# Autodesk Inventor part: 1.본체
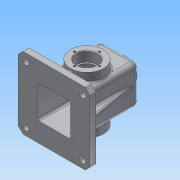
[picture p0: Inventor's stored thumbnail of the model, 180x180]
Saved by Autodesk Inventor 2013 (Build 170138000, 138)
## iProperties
Created: 2018-10
Part Number: 1.본체
Material: 알루미늄 6061
Document SubType Name: Modeling
Designer: Administrator
Density: 2.71 g/cm^3
Mass: 789.687 g
Surface Area: 898.798 cm^2
Volume: 291.397 cm^3
Author: Administrator
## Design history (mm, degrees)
sketch "스케치1"
  geometry: C1 r 27.5 at (0, 0); 1 further point
  constraints: 1 centre point, 1 coincident
  dimensions: "d0" = 55 diameter of C1
extrude "돌출1" new body sketch "스케치1" stored distance "d2" = 95; taper "d3" = 0 deg
node "작업 평면1"
sketch "스케치3"
  geometry: L1 (60, -60)-(-60, -60); L2 (-60, -60)-(-60, 60); L3 (-60, 60)-(60, 60); L4 (60, 60)-(60, -60); L5 (60, -60)-(-60, 60); L6 (-60, -60)-(60, 60); 1 further point
  constraints: 12 end point, 2 midpoint, 2 parallel, 1 horizontal, 1 perpendicular
  dimensions: "d5" = 120 distance of L1.start L1.end; "d7" = 120 distance of L1.end L2.end
extrude "돌출2" join sketch "스케치3" distance "d8" = 10; taper "d9" = 0 deg
sketch "스케치4"
  geometry: L1 (-32.5, 32.5)-(32.5, 32.5); L2 (32.5, 32.5)-(32.5, -32.5); L3 (32.5, -32.5)-(-32.5, -32.5); L4 (-32.5, -32.5)-(-32.5, 32.5); L5 (-32.5, 32.5)-(32.5, -32.5); L6 (32.5, 32.5)-(-32.5, -32.5); 1 further point
  constraints: 12 end point, 2 midpoint, 2 parallel, 1 horizontal, 1 perpendicular
  dimensions: "d10" = 65 distance of L1.start L1.end; "d12" = 65 distance of L1.end L2.end
extrude "돌출3" join sketch "스케치4" distance "d13" = 100; taper "d14" = 0 deg
chamfer "모따기1" distance "d15" = 8; stored, may be unused: second distance "d16" = 2, angle "d17" = 45 deg
sketch "스케치5"
  geometry: 3 further points
  dimensions: "d18" = 95 distance of point (47.5, 47.5) point (-47.5, 47.5); "d20" = 47.5 horizontal distance of point (-47.5, 47.5) point (0, 0); "d21" = 47.5 horizontal distance of point (0, 0) point (-47.5, 47.5); "d22" = 47.5 horizontal distance of point (0, 0) point (47.5, 47.5)
hole "구멍1" sketch "스케치5" at (-47.5, 47.5), (47.5, 47.5) diameter "d23" = 10; stored, may be unused: countersink angle "d27" = 90 deg, drill point angle "d29" = 118 deg; dims "d24" = 6, "d25" = 4, "d26" = 2, "d28" = 8
sketch "스케치6"
  geometry: L1 (-27.5, 27.5)-(27.5, 27.5); L2 (27.5, 27.5)-(27.5, -27.5); L3 (27.5, -27.5)-(-27.5, -27.5); L4 (-27.5, -27.5)-(-27.5, 27.5); L5 (-27.5, 27.5)-(27.5, -27.5); L6 (27.5, 27.5)-(-27.5, -27.5); 1 further point
  constraints: 12 end point, 2 midpoint, 2 parallel, 1 horizontal, 1 perpendicular
  dimensions: "d30" = 55 distance of L2.end L3.end; "d31" = 55 distance of L1.end L2.end
extrude "돌출4" cut sketch "스케치6" distance "d32" = 105; taper "d33" = 0 deg
sketch "스케치7"
  geometry: L1 (0, 0)-(21, 0); C1 r 27.5 at (0, 0) reference; 1 further point
  constraints: 2 end point, 1 coincident, 1 horizontal
  dimensions: "d34" = 21 distance of L1.start L1.end
hole "구멍2" sketch "스케치7" at (21, 0) diameter "d35" = 3.242; stored, may be unused: countersink angle "d39" = 90 deg, drill point angle "d41" = 118 deg; dims "d36" = 8, "d37" = 4, "d38" = 2, "d40" = 10
sketch "스케치9"
  geometry: C1 r 27.5 at (0, 0) reference
hole "구멍3" sketch "스케치9" at (0, 0) diameter "d45" = 30; stored, may be unused: countersink angle "d49" = 90 deg, drill point angle "d51" = 118 deg; dims "d46" = 8, "d47" = 35, "d48" = 17, "d50" = 10
sketch "스케치10"
  geometry: C1 r 15 at (0, 0) reference
hole "구멍4" sketch "스케치10" at (0, 0) diameter "d52" = 30; stored, may be unused: countersink angle "d56" = 90 deg, drill point angle "d58" = 118 deg; dims "d53" = 8, "d54" = 35, "d55" = 17, "d57" = 10
fillet "모깎기1" dims "d59" = 3
fillet "모깎기2" dims "d60" = 3
node "작업 평면2"
sketch "스케치11"
  geometry: C1 r 20 at (0, 0); 1 further point
  constraints: 1 centre point, 1 coincident
  dimensions: "d62" = 40 diameter of C1
extrude "돌출5" join sketch "스케치11" stored distance "d64" = 105; taper "d65" = 0 deg
feature "면 기울기1" dims angle "d66" = 7 deg
sketch "스케치13"
  geometry: L1 (32.5, 55)-(32.5, -45) reference; L2 (32.5, -45)-(60, -45) reference; L3 (60, -45)-(60, -55) reference; L4 (60, -55)-(27.5, -55) reference; L5 (27.5, -55)-(27.5, 47) reference; L6 (24.5, 50)-(-24.5, 50) reference; L7 (-18.772, 65)-(18.772, 65) reference; L8 (18.772, 65)-(20, 55) reference; L9 (20, 55)-(32.5, 55) reference; L10 (-32.5, -45)-(-32.5, 55) reference; L11 (-32.5, 55)-(-20, 55) reference; L12 (-20, 55)-(-18.772, 65) reference; L13 (-27.5, 47)-(-27.5, -55) reference; L14 (-27.5, -55)-(-60, -55) reference; L15 (-60, -55)-(-60, -45) reference; L16 (-60, -45)-(-32.5, -45) reference; L17 (-48, -45)-(-32.5, 42.905); A1 r 3 centre (24.5, 47) between (27.5, 47) and (24.5, 50) reference; A2 r 3 centre (-24.5, 47) between (-24.5, 50) and (-27.5, 47) reference; 1 further point
  constraints: 2 end point, 2 point on line
  dimensions: "d75" = 12 distance from line of L15 L17.start; "d76" = 100 deg angle of L16 L17
feature "리브1" sketch "스케치13" dims "d77" = 2, "d78" = 10, "d79" = 0, "d80" = 0, "d81" = 1, "d82" = 1
sketch "스케치14"
  geometry: L1 (-21, -36.526)-(-22.621, -37.5) reference; L2 (-22.621, -37.5)-(-22.621, -47.5) reference; L3 (-22.621, -47.5)-(-27.5, -47.5) reference; L4 (-27.5, -47.5)-(-27.5, -32.5) reference; L5 (-27.5, -32.5)-(-45, -32.5) reference; L6 (-45, -32.5)-(-45, -60) reference; L7 (-45, -60)-(-55, -60) reference; L8 (-55, -60)-(-55, -27.5) reference; L9 (-55, -27.5)-(-15, -27.5) reference; L10 (-15, -27.5)-(-15, -30.5) reference; L11 (-15, -30.5)-(-17.5, -30.5) reference; L12 (-17.5, -30.5)-(-17.5, -47.5) reference; L13 (-17.5, -47.5)-(-19.379, -47.5) reference; L14 (-19.379, -47.5)-(-19.379, -37.5) reference; L15 (-19.379, -37.5)-(-21, -36.526) reference; L16 (-22.621, 37.5)-(-21, 36.526) reference; L17 (-21, 36.526)-(-19.379, 37.5) reference; L18 (-19.379, 37.5)-(-19.379, 47.5) reference; L19 (-19.379, 47.5)-(-17.5, 47.5) reference; L20 (-17.5, 47.5)-(-17.5, 30.5) reference; L21 (-17.5, 30.5)-(-15, 30.5) reference; L22 (-15, 30.5)-(-15, 27.5) reference; L23 (-15, 27.5)-(-55, 27.5) reference; L24 (-55, 27.5)-(-55, 60) reference; L25 (-55, 60)-(-45, 60) reference; L26 (-45, 60)-(-45, 32.5) reference; L27 (-45, 32.5)-(-27.5, 32.5) reference; L28 (-27.5, 32.5)-(-27.5, 47.5) reference; L29 (-27.5, 47.5)-(-22.621, 47.5) reference; L30 (-22.621, 47.5)-(-22.621, 37.5) reference; L31 (27.5, 32.5)-(55, 32.5) reference; L32 (55, 32.5)-(55, 20) reference; L33 (55, 20)-(65, 18.772) reference; L34 (65, 18.772)-(65, -18.772) reference; L35 (50, -24.5)-(50, 24.5) reference; L36 (47, 27.5)-(15, 27.5) reference; L37 (15, 27.5)-(15, 30.5) reference; L38 (15, 30.5)-(17.5, 30.5) reference; L39 (17.5, 30.5)-(17.5, 47.5) reference; L40 (17.5, 47.5)-(19.379, 47.5) reference; L41 (19.379, 47.5)-(19.379, 37.5) reference; L42 (19.379, 37.5)-(21, 36.526) reference; L43 (21, 36.526)-(22.621, 37.5) reference; L44 (22.621, 37.5)-(22.621, 47.5) reference; L45 (22.621, 47.5)-(27.5, 47.5) reference; L46 (27.5, 47.5)-(27.5, 32.5) reference; L47 (55, -32.5)-(27.5, -32.5) reference; L48 (27.5, -32.5)-(27.5, -47.5) reference; L49 (27.5, -47.5)-(22.621, -47.5) reference; L50 (22.621, -47.5)-(22.621, -37.5) reference; L51 (22.621, -37.5)-(21, -36.526) reference; L52 (21, -36.526)-(19.379, -37.5) reference; L53 (19.379, -37.5)-(19.379, -47.5) reference; L54 (19.379, -47.5)-(17.5, -47.5) reference; L55 (17.5, -47.5)-(17.5, -30.5) reference; L56 (17.5, -30.5)-(15, -30.5) reference; L57 (15, -30.5)-(15, -27.5) reference; L58 (15, -27.5)-(47, -27.5) reference; L59 (65, -18.772)-(55, -20) reference; L60 (55, -20)-(55, -32.5) reference; L61 (-45, 42.5)-(-30.759, 42.5); A1 r 3 centre (47, 24.5) between (50, 24.5) and (47, 27.5) reference; A2 r 3 centre (47, -24.5) between (47, -27.5) and (50, -24.5) reference; 1 further point
  constraints: 2 end point, 1 perpendicular, 1 point on line
  dimensions: "d83" = 15 distance between parallel lines of L23 L61
feature "리브2" sketch "스케치14" dims "d84" = 2, "d85" = 6, "d86" = 0, "d87" = 0, "d88" = 1, "d89" = 1
fillet "모깎기3" dims "d90" = 3
fillet "모깎기4" dims "d91" = 0.3
fillet "모깎기5" dims "d92" = 8
fillet "모깎기6" dims "d93" = 8
fillet "모깎기7" dims "d94" = 3
fillet "모깎기8" dims "d95" = 3
fillet "모깎기9" dims "d96" = 3
fillet "모깎기10" dims "d97" = 1
chamfer "모따기2" distance "d98" = 1; stored, may be unused: second distance "d99" = 2, angle "d100" = 45 deg
sketch "스케치15"
  geometry: L1 (-8, 0)-(-8, -91) reference; L2 (5.728, 18)-(43.272, 18) reference; 1 further point
  constraints: 1 other
  dimensions: "d101" = 32.5 distance from line of point (24.5, -8) L1; "d102" = 26 distance from line of L2 point (24.5, -8)
feature "엠보싱1" sketch "스케치15" dims "d0" = 55, "d103" = 0.5, "d104" = 0
fillet "모깎기11" dims "d105" = 3
hole "구멍5" diameter "d111" = 22.835; stored, may be unused: countersink angle "d115" = 90 deg, drill point angle "d117" = 118 deg; dims "d109" = 10, "d110" = 10, "d112" = 30, "d113" = 35, "d114" = 17, "d116" = 10
node "솔리드1"
mirror "대칭1"
pattern_circular "원형 패턴1" dims angle "d43" = 360 deg
mirror "대칭2"
mirror "대칭3"
mirror "대칭4"
node "절단 모서리 투영1"
node "절단 모서리 투영2"
other parameters: "d4" = -55
